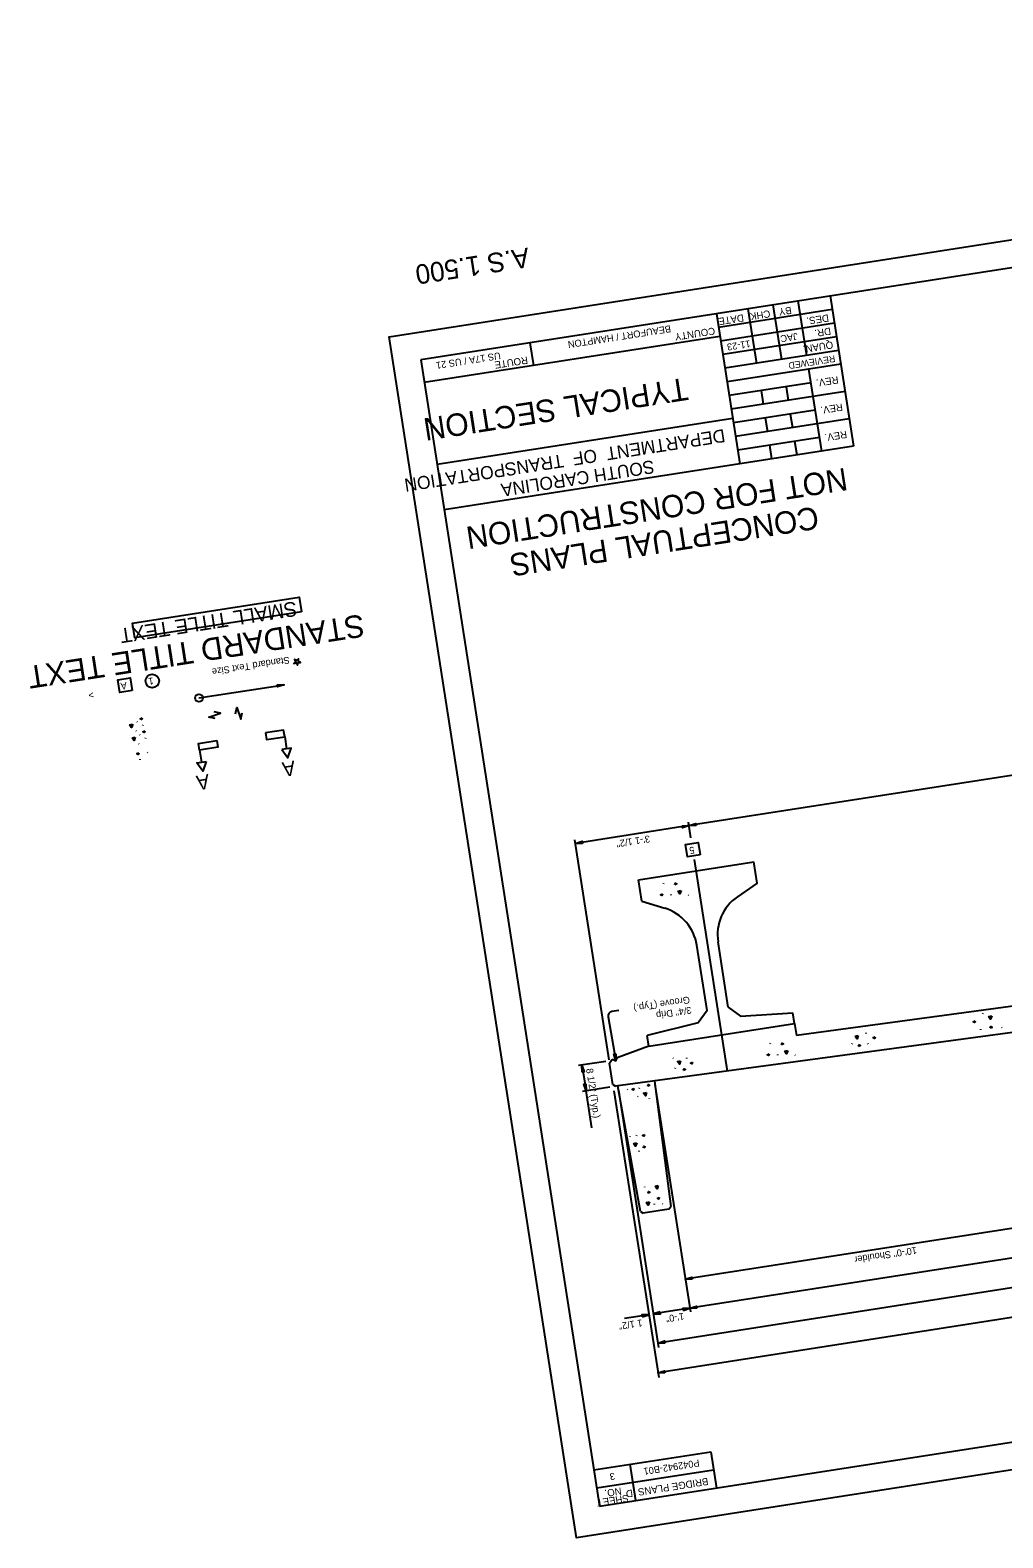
# Model space of a CAD drawing. Extents: x 2107312.3 to 2107380.5, y 591445.7 to 591486.7.
# Drawn here: x 2107312.26 to 2107338.67, y 591445.74 to 591486.67 of the extents above; entities that cross this region are included whole.
import ezdxf

# ---------------------------------------------------------------- set-up
doc = ezdxf.new("R2010")
doc.units = 0
for name, color, linetype in [('BR_AUTO DIMENSION', 7, 'Continuous'), ('BR_BORDER LINES', 7, 'Continuous'), ('BR_CENTER LINES', 7, 'Continuous'), ('BR_CONCRETE', 7, 'Continuous'), ('BR_PRESTRESSED BEAM', 7, 'Continuous'), ('BR_TABLE LINES', 7, 'Continuous'), ('BR_TEXT', 7, 'Continuous'), ('RD_SHT_IplotShp', 7, 'Continuous')]:
    doc.layers.add(name, color=color, linetype=linetype)

msp = doc.modelspace()

# ---------------------------------------------------------------- linework, layer by layer
at = {"layer": 'BR_AUTO DIMENSION'}
for p, q in [((2107369.675, 591471.241), (2107330.153, 591465.074)), ((2107316.847, 591468.541), (2107319.157, 591468.901)), ((2107330.153, 591465.074), (2107327.066, 591464.592)), ((2107330.205, 591464.742), (2107330.139, 591465.166)), ((2107327.982, 591458.72), (2107327.051, 591464.685)), ((2107327.955, 591459.88), (2107328.168, 591458.69)), ((2107328.25, 591460.055), (2107328.059, 591460.025)), ((2107327.894, 591458.675), (2107327.153, 591458.559)), ((2107327.245, 591458.573), (2107327.355, 591457.874)), ((2107328.003, 591457.975), (2107327.262, 591457.859)), ((2107327.511, 591456.874), (2107327.355, 591457.874)), ((2107328.114, 591457.874), (2107329.328, 591450.097)), ((2107328.238, 591457.894), (2107329.327, 591450.909)), ((2107329.226, 591458.048), (2107330.188, 591451.878)), ((2107373.771, 591457.966), (2107329.309, 591451.028)), ((2107375.005, 591457.351), (2107329.308, 591450.221)), ((2107351.911, 591455.363), (2107330.174, 591451.971)), ((2107339.931, 591454.301), (2107330.051, 591452.759)), ((2107329.062, 591451.797), (2107328.398, 591451.694)), ((2107330.174, 591451.971), (2107329.186, 591451.817))]:
    msp.add_line(p, q, dxfattribs=at)
for points in [[(2107318.967, 591468.9), (2107319.157, 591468.901), (2107318.976, 591468.844)], [(2107329.964, 591465.073), (2107330.153, 591465.074), (2107329.972, 591465.017)], [(2107330.343, 591465.075), (2107330.153, 591465.074), (2107330.334, 591465.13)], [(2107327.255, 591464.593), (2107327.066, 591464.592), (2107327.247, 591464.649)], [(2107328.163, 591458.879), (2107328.168, 591458.69), (2107328.107, 591458.869)], [(2107327.246, 591458.384), (2107327.245, 591458.573), (2107327.302, 591458.392)], [(2107327.353, 591458.063), (2107327.355, 591457.874), (2107327.298, 591458.054)], [(2107330.24, 591452.76), (2107330.051, 591452.759), (2107330.232, 591452.816)], [(2107328.881, 591451.741), (2107329.062, 591451.797), (2107328.873, 591451.796)], [(2107329.367, 591451.873), (2107329.186, 591451.817), (2107329.375, 591451.818)], [(2107329.993, 591451.914), (2107330.174, 591451.971), (2107329.984, 591451.97)], [(2107330.363, 591451.972), (2107330.174, 591451.971), (2107330.355, 591452.027)], [(2107329.498, 591451.029), (2107329.309, 591451.028), (2107329.49, 591451.085)], [(2107329.498, 591450.222), (2107329.308, 591450.221), (2107329.489, 591450.277)]]:
    msp.add_lwpolyline(points, close=True, dxfattribs=at)
msp.add_circle((2107316.847, 591468.541), 0.106, dxfattribs=at)
msp.add_arc((2107328.078, 591459.902), 0.125, 98.8692, 190.1462, dxfattribs=at)
at = {"layer": 'BR_BORDER LINES'}
for p, q in [((2107372.763, 591485.506), (2107322.867, 591477.72)), ((2107332.67, 591477.731), (2107332.438, 591479.213)), ((2107333.349, 591477.837), (2107333.118, 591479.319)), ((2107333.982, 591479.454), (2107334.618, 591475.378)), ((2107330.894, 591478.972), (2107331.53, 591474.897)), ((2107334.04, 591479.084), (2107330.952, 591478.602)), ((2107334.098, 591478.713), (2107331.01, 591478.231)), ((2107331.99, 591477.625), (2107331.759, 591479.107)), ((2107330.991, 591478.355), (2107322.963, 591477.102)), ((2107334.156, 591478.343), (2107331.068, 591477.861)), ((2107325.831, 591478.182), (2107325.927, 591477.565)), ((2107334.213, 591477.972), (2107331.126, 591477.49)), ((2107322.867, 591477.72), (2107327.723, 591446.596)), ((2107334.271, 591477.602), (2107331.184, 591477.12)), ((2107333.464, 591477.096), (2107331.241, 591476.749)), ((2107333.754, 591475.244), (2107333.407, 591477.467)), ((2107334.387, 591476.86), (2107331.299, 591476.379)), ((2107332.106, 591476.884), (2107332.164, 591476.514)), ((2107332.785, 591476.99), (2107332.843, 591476.62)), ((2107333.58, 591476.355), (2107331.357, 591476.008)), ((2107332.901, 591476.249), (2107332.959, 591475.879)), ((2107331.338, 591476.132), (2107323.31, 591474.879)), ((2107331.338, 591476.132), (2107331.338, 591476.132)), ((2107334.502, 591476.119), (2107331.415, 591475.638)), ((2107332.222, 591476.143), (2107332.279, 591475.773)), ((2107333.696, 591475.614), (2107331.473, 591475.267)), ((2107333.016, 591475.508), (2107333.074, 591475.138)), ((2107334.618, 591475.378), (2107323.503, 591473.644)), ((2107332.337, 591475.402), (2107332.395, 591475.032)), ((2107323.31, 591474.879), (2107323.31, 591474.879)), ((2107327.723, 591446.596), (2107377.619, 591454.382)), ((2107327.569, 591447.584), (2107330.741, 591448.079)), ((2107330.741, 591448.079), (2107330.895, 591447.091)), ((2107328.547, 591447.737), (2107328.701, 591446.749)), ((2107330.819, 591447.58), (2107327.647, 591447.085))]:
    msp.add_line(p, q, dxfattribs=at)
at = {"layer": 'BR_CENTER LINES'}
for p, q in [((2107315.181, 591467.882), (2107315.173, 591467.89)), ((2107315.32, 591467.809), (2107315.316, 591467.793)), ((2107315.152, 591467.638), (2107315.144, 591467.647)), ((2107315.224, 591467.285), (2107315.216, 591467.294)), ((2107315.252, 591467.528), (2107315.245, 591467.537)), ((2107315.392, 591467.456), (2107315.388, 591467.439)), ((2107315.241, 591466.881), (2107315.237, 591466.864)), ((2107315.455, 591467.049), (2107315.451, 591467.063)), ((2107331.193, 591458.409), (2107330.297, 591464.156)), ((2107329.458, 591463.51), (2107329.453, 591463.494)), ((2107329.661, 591463.208), (2107329.657, 591463.191)), ((2107330.144, 591463.179), (2107330.136, 591463.189)), ((2107338.127, 591459.985), (2107338.122, 591459.969)), ((2107338.065, 591459.549), (2107338.061, 591459.533)), ((2107338.651, 591459.585), (2107338.643, 591459.595)), ((2107332.353, 591459.165), (2107332.348, 591459.148)), ((2107334.579, 591459.162), (2107334.575, 591459.145)), ((2107334.954, 591459.452), (2107334.95, 591459.436)), ((2107335.011, 591459.146), (2107335.003, 591459.156)), ((2107329.731, 591458.749), (2107329.723, 591458.758)), ((2107330.086, 591458.768), (2107330.081, 591458.752)), ((2107332.556, 591458.862), (2107332.551, 591458.846)), ((2107333.039, 591458.833), (2107333.031, 591458.843)), ((2107329.772, 591458.498), (2107329.768, 591458.481)), ((2107328.489, 591457.902), (2107328.481, 591457.912)), ((2107328.795, 591457.957), (2107328.79, 591457.941)), ((2107328.761, 591457.725), (2107328.756, 591457.709)), ((2107329.082, 591457.66), (2107329.074, 591457.67)), ((2107328.558, 591456.629), (2107328.55, 591456.639)), ((2107328.726, 591456.673), (2107328.721, 591456.657)), ((2107328.792, 591456.247), (2107328.788, 591456.23)), ((2107328.944, 591455.272), (2107328.94, 591455.256)), ((2107329.206, 591454.806), (2107329.201, 591454.79)), ((2107329.437, 591454.797), (2107329.429, 591454.807))]:
    msp.add_line(p, q, dxfattribs=at)
for points in [[(2107317.286, 591467.981), (2107317.114, 591468.016), (2107317.429, 591468.128), (2107317.258, 591468.163)], [(2107317.836, 591468.112), (2107317.872, 591468.283), (2107317.983, 591467.968), (2107318.018, 591468.14)], [(2107315.048, 591467.83), (2107315.016, 591467.737), (2107314.968, 591467.811), (2107315.046, 591467.829)], [(2107315.303, 591467.999), (2107315.289, 591467.954), (2107315.252, 591467.974), (2107315.303, 591467.999)], [(2107315.119, 591467.477), (2107315.087, 591467.385), (2107315.04, 591467.457), (2107315.117, 591467.476)], [(2107315.374, 591467.646), (2107315.361, 591467.601), (2107315.324, 591467.621), (2107315.374, 591467.646)], [(2107315.211, 591467.055), (2107315.198, 591467.01), (2107315.161, 591467.03), (2107315.211, 591467.055)], [(2107329.431, 591463.224), (2107329.417, 591463.18), (2107329.38, 591463.199), (2107329.431, 591463.224)], [(2107329.77, 591463.472), (2107329.784, 591463.517), (2107329.821, 591463.497), (2107329.77, 591463.472)], [(2107329.935, 591463.318), (2107329.903, 591463.226), (2107329.856, 591463.299), (2107329.933, 591463.318)], [(2107338.371, 591459.913), (2107338.339, 591459.821), (2107338.291, 591459.894), (2107338.369, 591459.912)], [(2107337.916, 591459.772), (2107337.902, 591459.728), (2107337.865, 591459.748), (2107337.916, 591459.772)], [(2107338.33, 591459.574), (2107338.344, 591459.618), (2107338.381, 591459.598), (2107338.33, 591459.574)], [(2107332.665, 591459.127), (2107332.679, 591459.171), (2107332.716, 591459.151), (2107332.665, 591459.127)], [(2107334.748, 591459.376), (2107334.716, 591459.284), (2107334.668, 591459.357), (2107334.746, 591459.375)], [(2107334.753, 591459.08), (2107334.767, 591459.125), (2107334.803, 591459.105), (2107334.753, 591459.08)], [(2107335.201, 591459.343), (2107335.187, 591459.299), (2107335.151, 591459.319), (2107335.201, 591459.343)], [(2107329.922, 591458.689), (2107329.89, 591458.597), (2107329.842, 591458.67), (2107329.92, 591458.688)], [(2107330.243, 591458.651), (2107330.229, 591458.606), (2107330.192, 591458.626), (2107330.243, 591458.651)], [(2107332.325, 591458.878), (2107332.312, 591458.834), (2107332.275, 591458.854), (2107332.325, 591458.878)], [(2107332.83, 591458.972), (2107332.798, 591458.88), (2107332.75, 591458.954), (2107332.828, 591458.972)], [(2107330.004, 591458.425), (2107330.018, 591458.47), (2107330.054, 591458.45), (2107330.004, 591458.425)], [(2107328.656, 591457.939), (2107328.642, 591457.895), (2107328.605, 591457.914), (2107328.656, 591457.939)], [(2107329.03, 591457.998), (2107329.044, 591458.043), (2107329.081, 591458.023), (2107329.03, 591457.998)], [(2107328.999, 591457.827), (2107328.968, 591457.735), (2107328.92, 591457.808), (2107328.998, 591457.827)], [(2107328.942, 591456.689), (2107328.929, 591456.645), (2107328.892, 591456.664), (2107328.942, 591456.689)], [(2107328.731, 591456.464), (2107328.699, 591456.372), (2107328.652, 591456.445), (2107328.729, 591456.464)], [(2107328.913, 591456.33), (2107328.927, 591456.374), (2107328.964, 591456.354), (2107328.913, 591456.33)], [(2107329.04, 591455.099), (2107329.054, 591455.143), (2107329.091, 591455.124), (2107329.04, 591455.099)], [(2107329.317, 591455.309), (2107329.285, 591455.217), (2107329.237, 591455.29), (2107329.315, 591455.309)], [(2107329.344, 591454.977), (2107329.33, 591454.933), (2107329.294, 591454.953), (2107329.344, 591454.977)], [(2107329.076, 591454.865), (2107329.045, 591454.773), (2107328.997, 591454.846), (2107329.075, 591454.865)]]:
    msp.add_lwpolyline(points, dxfattribs=at)
at = {"layer": 'BR_CONCRETE'}
for p, q in [((2107351.016, 591461.098), (2107328.158, 591457.998)), ((2107339.013, 591460.184), (2107333.066, 591459.378)), ((2107333.015, 591459.706), (2107333.066, 591459.378)), ((2107329.063, 591459.089), (2107328.205, 591458.77)), ((2107327.997, 591458.627), (2107328.045, 591458.711)), ((2107328.088, 591458.727), (2107328.045, 591458.711)), ((2107328.088, 591458.727), (2107328.168, 591458.69)), ((2107328.168, 591458.69), (2107328.205, 591458.77)), ((2107328.086, 591458.051), (2107327.997, 591458.627)), ((2107328.086, 591458.051), (2107328.158, 591457.998)), ((2107328.834, 591454.602), (2107328.22, 591458.006)), ((2107329.211, 591458.14), (2107329.66, 591454.731)), ((2107328.834, 591454.602), (2107328.907, 591454.551)), ((2107329.607, 591454.66), (2107328.907, 591454.551)), ((2107329.607, 591454.66), (2107329.66, 591454.731))]:
    msp.add_line(p, q, dxfattribs=at)
at = {"layer": 'BR_PRESTRESSED BEAM'}
for p, q in [((2107328.781, 591463.599), (2107331.91, 591464.088)), ((2107332, 591463.511), (2107331.91, 591464.088)), ((2107328.871, 591463.023), (2107328.781, 591463.599)), ((2107332, 591463.511), (2107331.464, 591463.141)), ((2107328.871, 591463.023), (2107329.494, 591462.833)), ((2107330.642, 591460.052), (2107330.364, 591461.83)), ((2107331.218, 591460.142), (2107330.941, 591461.92)), ((2107330.642, 591460.052), (2107330.399, 591459.719)), ((2107331.218, 591460.142), (2107331.551, 591459.899)), ((2107331.551, 591459.899), (2107332.97, 591459.994)), ((2107333.015, 591459.706), (2107332.97, 591459.994)), ((2107330.399, 591459.719), (2107329.018, 591459.377)), ((2107329.063, 591459.089), (2107333.015, 591459.706)), ((2107329.063, 591459.089), (2107329.018, 591459.377))]:
    msp.add_line(p, q, dxfattribs=at)
for centre, start, end in [((2107329.129, 591461.638), 8.8692, 73.0482), ((2107332.176, 591462.113), 124.6901, 188.8692)]:
    msp.add_arc(centre, 1.25, start, end, dxfattribs=at)
at = {"layer": 'BR_TABLE LINES'}
for p, q in [((2107319.174, 591467.487), (2107319.225, 591467.158)), ((2107316.863, 591467.126), (2107316.914, 591466.797))]:
    msp.add_line(p, q, dxfattribs=at)
for points in [[(2107319.63, 591470.875), (2107315.105, 591470.169), (2107315.043, 591470.569), (2107319.567, 591471.275)], [(2107318.651, 591467.591), (2107318.679, 591467.41), (2107319.174, 591467.487), (2107319.145, 591467.668)], [(2107317.329, 591467.385), (2107317.357, 591467.203), (2107316.863, 591467.126), (2107316.835, 591467.308)], [(2107319.101, 591467.138), (2107319.263, 591466.911), (2107319.348, 591467.177)], [(2107317.038, 591466.816), (2107316.953, 591466.55), (2107316.791, 591466.778)]]:
    msp.add_lwpolyline(points, close=True, dxfattribs=at)
at = {"layer": 'BR_TEXT'}
for points in [[(2107319.539, 591469.537), (2107319.55, 591469.605), (2107319.502, 591469.557), (2107319.443, 591469.588), (2107319.473, 591469.529), (2107319.423, 591469.48), (2107319.491, 591469.49), (2107319.52, 591469.431), (2107319.532, 591469.496), (2107319.6, 591469.507)], [(2107315.035, 591468.744), (2107314.694, 591468.69), (2107314.641, 591469.031), (2107314.982, 591469.084)], [(2107330.452, 591464.278), (2107330.111, 591464.225), (2107330.058, 591464.566), (2107330.399, 591464.619)]]:
    msp.add_lwpolyline(points, close=True, dxfattribs=at)
msp.add_circle((2107315.579, 591469.003), 0.184, dxfattribs=at)
at = {"layer": 'RD_SHT_IplotShp'}
msp.add_lwpolyline([(2107380.452, 591454.065), (2107327.098, 591445.739), (2107322.01, 591478.345), (2107375.364, 591486.671)], close=True, dxfattribs=at)

# ---------------------------------------------------------------- texts
at = {"layer": 'BR_AUTO DIMENSION'}
for s, rotation, p in [('3\'-1 1/2"', 188.8692, (2107329.077, 591464.811)), ('8 1/2"', 278.8692, (2107327.356, 591458.47)), ('(Typ.)', 278.8692, (2107327.466, 591457.77))]:
    msp.add_text(s, height=0.1875, rotation=rotation, dxfattribs=at).set_placement(p)
at = {"layer": 'BR_TEXT'}
for s, height, p in [('A.S 1.500', 0.5312, (2107325.773, 591480.768)), ('BY', 0.195, (2107332.921, 591479.164)), ('DATE', 0.195, (2107331.623, 591478.959)), ('CHK.', 0.195, (2107332.342, 591479.072)), ('DES.', 0.195, (2107333.931, 591478.957)), ('BEAUFORT / HAMPTON', 0.1875, (2107329.644, 591478.659)), ('COUNTY', 0.195, (2107330.842, 591478.604)), ('JAC', 0.1875, (2107333.087, 591478.454)), ('DR.', 0.195, (2107333.989, 591478.599)), ('US 17A / US 21', 0.1875, (2107325.021, 591477.929)), ('11-23', 0.1875, (2107331.805, 591478.254)), ('QUAN.', 0.195, (2107334.047, 591478.227)), ('ROUTE', 0.195, (2107325.761, 591477.811)), ('REVIEWED', 0.18, (2107334.106, 591477.844)), ('TYPICAL SECTION', 0.60938, (2107330.066, 591477.24)), ('REV.', 0.195, (2107334.193, 591477.277)), ('REV.', 0.195, (2107334.309, 591476.536)), ('DEPARTMENT  OF  TRANSPORTATION', 0.35378, (2107331.102, 591475.843)), ('REV.', 0.195, (2107334.424, 591475.795)), ('NOT FOR CONSTRUCTION', 0.60938, (2107334.398, 591474.792)), ('SOUTH CAROLINA', 0.35378, (2107329.18, 591475)), ('CONCEPTUAL PLANS', 0.60938, (2107333.619, 591473.745)), ('SMALL TITLE TEXT', 0.39845, (2107319.473, 591471.168)), ('STANDARD TITLE TEXT', 0.60938, (2107321.288, 591470.818)), ('Standard Text Size', 0.1875, (2107319.293, 591469.665)), ('A', 0.188, (2107314.874, 591468.975)), ('1', 0.188, (2107315.6, 591469.102)), ('>', 0.188, (2107313.98, 591468.718)), ('A', 0.398, (2107319.433, 591466.842)), ('A', 0.398, (2107317.101, 591466.478)), ('5', 0.187, (2107330.285, 591464.508)), ('Groove (Typ.) ', 0.1875, (2107330.159, 591460.441)), ('3/4" Drip', 0.1875, (2107330.202, 591460.163)), ('10\'-0" Shoulder', 0.1875, (2107336.32, 591453.642)), ('1\'-0"', 0.1875, (2107330.005, 591451.849)), ('1 1/2"', 0.1875, (2107328.87, 591451.672)), ('P042942-B01', 0.1875, (2107330.42, 591447.868)), ('3', 0.188, (2107328.126, 591447.51)), ('BRIDGE PLANS ID', 0.195, (2107330.659, 591447.372)), ('SHEET', 0.195, (2107328.497, 591446.915)), ('NO.', 0.195, (2107328.303, 591447.109))]:
    msp.add_text(s, height=height, rotation=188.8692, dxfattribs=at).set_placement(p)

doc.saveas('drawing.dxf')
